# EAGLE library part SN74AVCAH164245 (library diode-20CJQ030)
Ti's SN74AVCAH164245 16-BIT DUAL-SUPPLY BUS TRANSCEIVER WITH CONFIGURABLE VOLTAGE TRANSLATION AND 3-STATE OUTPUTS Description: This 16-bit (dual-octal) noninverting bus transceiver uses two separate configurable power-supply rails. The A-port is designed to track VCCA. VCCA accepts any supply voltage from 1.4 V to 3.6 V. The B-port is designed to track VCCB. VCCB accepts any supply voltage from 1.4 V to 3.6 V. This allows for universal low-voltage bidirectional translation between any of the 1.5-V, 1.8-V, 2.5-V, and 3.3-V voltage nodes. The SN74AVCAH164245 is designed for asynchronous communication between data buses. The device transmits data from the A bus to the B bus or from the B bus to the A bus, depending on the logic level at the direction-control (DIR) input. The output-enable (OE) input can be used to disable the outputs so the buses are effectively isolated. The SN74AVCAH164245 is designed so that the control pins (1DIR, 2DIR, 1OE, and 2OE) are supplied by VCCA. Active bus-hold circuitry is provided to hold unused or floating data inputs at a valid logic level. Use of pullup or pulldown resistors with the bus-hold circuitry is not recommended. To ensure the high-impedance state during power up or power down, OE should be tied to VCCA through a pullup resistor; the minimum value of the resistor is determined by the current-sinking capability of the driver. This device is fully specified for partial-power-down applications using Ioff. The Ioff circuitry disables the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
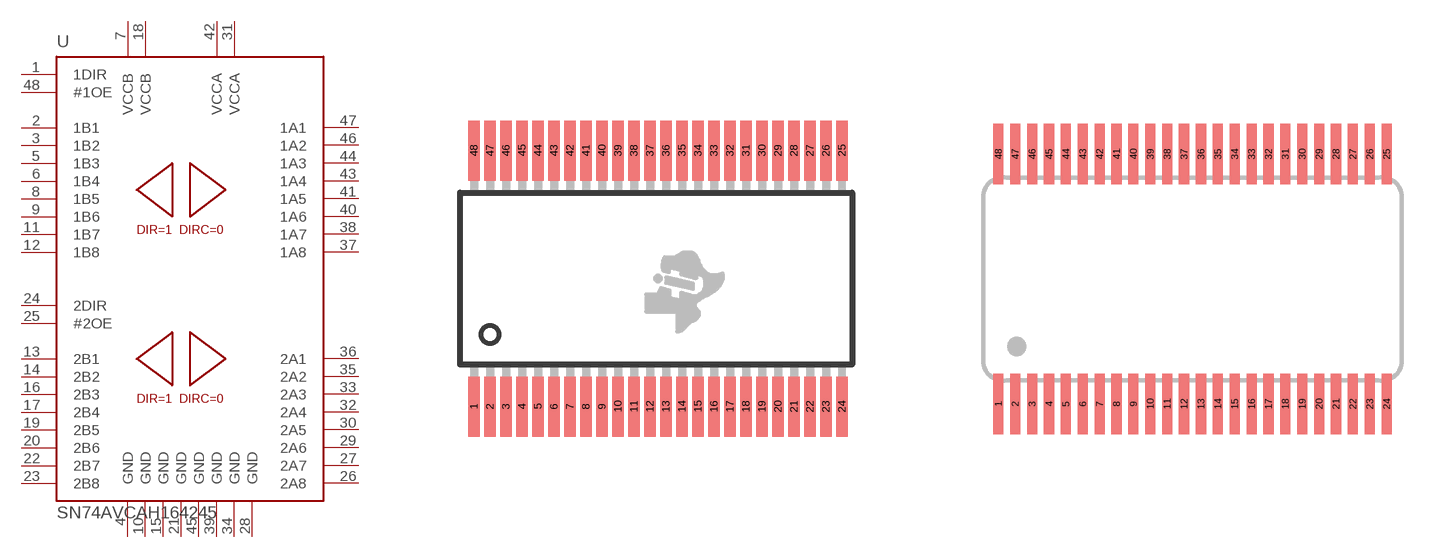
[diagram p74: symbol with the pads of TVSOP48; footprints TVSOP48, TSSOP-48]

Designator prefix U

## SN74AVCAH164245-DGV  [TVSOP48]
1  1DIR  in
2  1B1
3  1B2
4  GND  pwr
5  1B3
6  1B4
7  VCCB  pwr
8  1B5
9  1B6
10  GND  pwr
11  1B7
12  1B8
13  2B1
14  2B2
15  GND  pwr
16  2B3
17  2B4
18  VCCB  pwr
19  2B5
20  2B6
21  GND  pwr
22  2B7
23  2B8
24  2DIR  in
25  #2OE  in
26  2A8
27  2A7
28  GND  pwr
29  2A6
30  2A5
31  VCCA  pwr
32  2A4
33  2A3
34  GND  pwr
35  2A2
36  2A1
37  1A8
38  1A7
39  GND  pwr
40  1A6
41  1A5
42  VCCA  pwr
43  1A4
44  1A3
45  GND  pwr
46  1A2
47  1A1
48  #1OE  in

## SN74AVCAH164245-DGG  [TSSOP-48]
Pads as for TVSOP48

## SN74AVCAH164245-GQL  [VFBGA56]
A1  1DIR  in
A6  #1OE  in
B1  1B2
B2  1B1
B3  GND  pwr
B4  GND  pwr
B5  1A1
B6  1A2
C1  1B4
C2  1B3
C3  VCCB  pwr
C4  VCCA  pwr
C5  1A3
C6  1A4
D1  1B6
D2  1B5
D3  GND  pwr
D4  GND  pwr
D5  1A5
D6  1A6
E1  1B8
E2  1B7
E5  1A7
E6  1A8
F1  2B1
F2  2B2
F5  2A2
F6  2A1
G1  2B3
G2  2B4
G3  GND  pwr
G4  GND  pwr
G5  2A4
G6  2A3
H1  2B5
H2  2B6
H3  VCCB  pwr
H4  VCCA  pwr
H5  2A6
H6  2A5
J1  2B7
J2  2B8
J3  GND  pwr
J4  GND  pwr
J5  2A8
J6  2A7
K1  2DIR  in
K6  #2OE  in

## SN74AVCAH164245-ZQL  [VFBGA56]
Pads as for VFBGA56

## Footprint TVSOP48 (pad centres in mm)
Plastic Small Outline
smd 0.28 x 1.5: 1 -4.6,-3.2; 2 -4.2,-3.2; 3 -3.8,-3.2; 4 -3.4,-3.2; 5 -3,-3.2; 6 -2.6,-3.2; 7 -2.2,-3.2; 8 -1.8,-3.2; 9 -1.4,-3.2; 10 -1,-3.2; 11 -0.6,-3.2; 12 -0.2,-3.2; 13 0.2,-3.2; 14 0.6,-3.2; 15 1,-3.2; 16 1.4,-3.2; 17 1.8,-3.2; 18 2.2,-3.2; 19 2.6,-3.2; 20 3,-3.2; 21 3.4,-3.2; 22 3.8,-3.2; 23 4.2,-3.2; 24 4.6,-3.2; 25 4.6,3.2; 26 4.2,3.2; 27 3.8,3.2; 28 3.4,3.2; 29 3,3.2; 30 2.6,3.2; 31 2.2,3.2; 32 1.8,3.2; 33 1.4,3.2; 34 1,3.2; 35 0.6,3.2; 36 0.2,3.2; 37 -0.2,3.2; 38 -0.6,3.2; 39 -1,3.2; 40 -1.4,3.2; 41 -1.8,3.2; 42 -2.2,3.2; 43 -2.6,3.2; 44 -3,3.2; 45 -3.4,3.2; 46 -3.8,3.2; 47 -4.2,3.2; 48 -4.6,3.2

## Footprint TSSOP-48 (pad centres in mm)
smd 0.3 x 1.8: 1 -5.75,-3.7; 2 -5.25,-3.7; 3 -4.75,-3.7; 4 -4.25,-3.7; 5 -3.75,-3.7; 6 -3.25,-3.7; 7 -2.75,-3.7; 8 -2.25,-3.7; 9 -1.75,-3.7; 10 -1.25,-3.7; 11 -0.75,-3.7; 12 -0.25,-3.7; 13 0.25,-3.7; 14 0.75,-3.7; 15 1.25,-3.7; 16 1.75,-3.7; 17 2.25,-3.7; 18 2.75,-3.7; 19 3.25,-3.7; 20 3.75,-3.7; 21 4.25,-3.7; 22 4.75,-3.7; 23 5.25,-3.7; 24 5.75,-3.7; 25 5.75,3.7; 26 5.25,3.7; 27 4.75,3.7; 28 4.25,3.7; 29 3.75,3.7; 30 3.25,3.7; 31 2.75,3.7; 32 2.25,3.7; 33 1.75,3.7; 34 1.25,3.7; 35 0.75,3.7; 36 0.25,3.7; 37 -0.25,3.7; 38 -0.75,3.7; 39 -1.25,3.7; 40 -1.75,3.7; 41 -2.25,3.7; 42 -2.75,3.7; 43 -3.25,3.7; 44 -3.75,3.7; 45 -4.25,3.7; 46 -4.75,3.7; 47 -5.25,3.7; 48 -5.75,3.7

## Footprint VFBGA56 (pad centres in mm)
VFBGA56 from Ti (E.g. SN74AVCAH164245 )
smd 0.45 x 0.45: A1 1.625,-2.925; A2 0.975,-2.925; A3 0.325,-2.925; A4 -0.325,-2.925; A5 -0.975,-2.925; A6 -1.625,-2.925; B1 1.625,-2.275; B2 0.975,-2.275; B3 0.325,-2.275; B4 -0.325,-2.275; B5 -0.975,-2.275; B6 -1.625,-2.275; C1 1.625,-1.625; C2 0.975,-1.625; C3 0.325,-1.625; C4 -0.325,-1.625; C5 -0.975,-1.625; C6 -1.625,-1.625; D1 1.625,-0.975; D2 0.975,-0.975; D3 0.325,-0.975; D4 -0.325,-0.975; D5 -0.975,-0.975; D6 -1.625,-0.975; E1 1.625,-0.325; E2 0.975,-0.325; E5 -0.975,-0.325; E6 -1.625,-0.325; F1 1.625,0.325; F2 0.975,0.325; F5 -0.975,0.325; F6 -1.625,0.325; G1 1.625,0.975; G2 0.975,0.975; G3 0.325,0.975; G4 -0.325,0.975; G5 -0.975,0.975; G6 -1.625,0.975; H1 1.625,1.625; H2 0.975,1.625; H3 0.325,1.625; H4 -0.325,1.625; H5 -0.975,1.625; H6 -1.625,1.625; J1 1.625,2.275; J2 0.975,2.275; J3 0.325,2.275; J4 -0.325,2.275; J5 -0.975,2.275; J6 -1.625,2.275; K1 1.625,2.925; K2 0.975,2.925; K3 0.325,2.925; K4 -0.325,2.925; K5 -0.975,2.925; K6 -1.625,2.925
